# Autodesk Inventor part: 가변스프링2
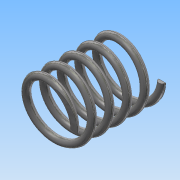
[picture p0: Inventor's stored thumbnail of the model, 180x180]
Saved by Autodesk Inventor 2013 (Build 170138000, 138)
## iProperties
Created: 2018-10
Part Number: 가변스프링2
Material: 스테인리스강
Document SubType Name: Modeling
Designer: Administrator
Density: 8.08 g/cm^3
Mass: 6.27241 g
Surface Area: 15.7591 cm^2
Volume: 0.776288 cm^3
Author: Administrator
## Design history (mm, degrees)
sketch "스케치1"
  geometry: L1 (0, 0)-(0, -24.937); L2 (0, 0)-(8, 0); L3 (0, -24.937)-(8, -24.937); C1 r 1 at (8, 0); 1 further point
  constraints: 6 end point, 2 coincident, 1 centre point, 1 parallel, 1 perpendicular, 1 vertical
  dimensions: "d0" = 24.93674 distance of L1.start L1.end (derived); "d2" = 8 distance of L1.start L2.end; "d3" = 2 diameter of C1
feature "코일1" sketch "스케치1" pitch "d4" = 10; turns "d6" = 5; dims "d5" = 24.93674 (= d0), "d7" = 0, angle "d8" = 90 deg, angle "d9" = 90 deg, "d10" = 0, "d11" = 0
sketch "스케치2"
  geometry: L1 (-24.937, 10)-(0, 10); L2 (0, 10)-(0, -10); L3 (0, -10)-(-24.937, -10); L4 (-24.937, -10)-(-24.937, 10); 2 further points
  constraints: 8 end point, 2 parallel, 1 coincident, 1 horizontal, 1 midpoint, 1 perpendicular
  dimensions: "d12" = 20 distance of L1.end L2.end; "d15" = 24.93674 distance of L2.end L3.end (derived)
extrude "돌출1" sketch "스케치2" stored distance "d16" = 0; taper "d17" = 0 deg
node "솔리드1"
